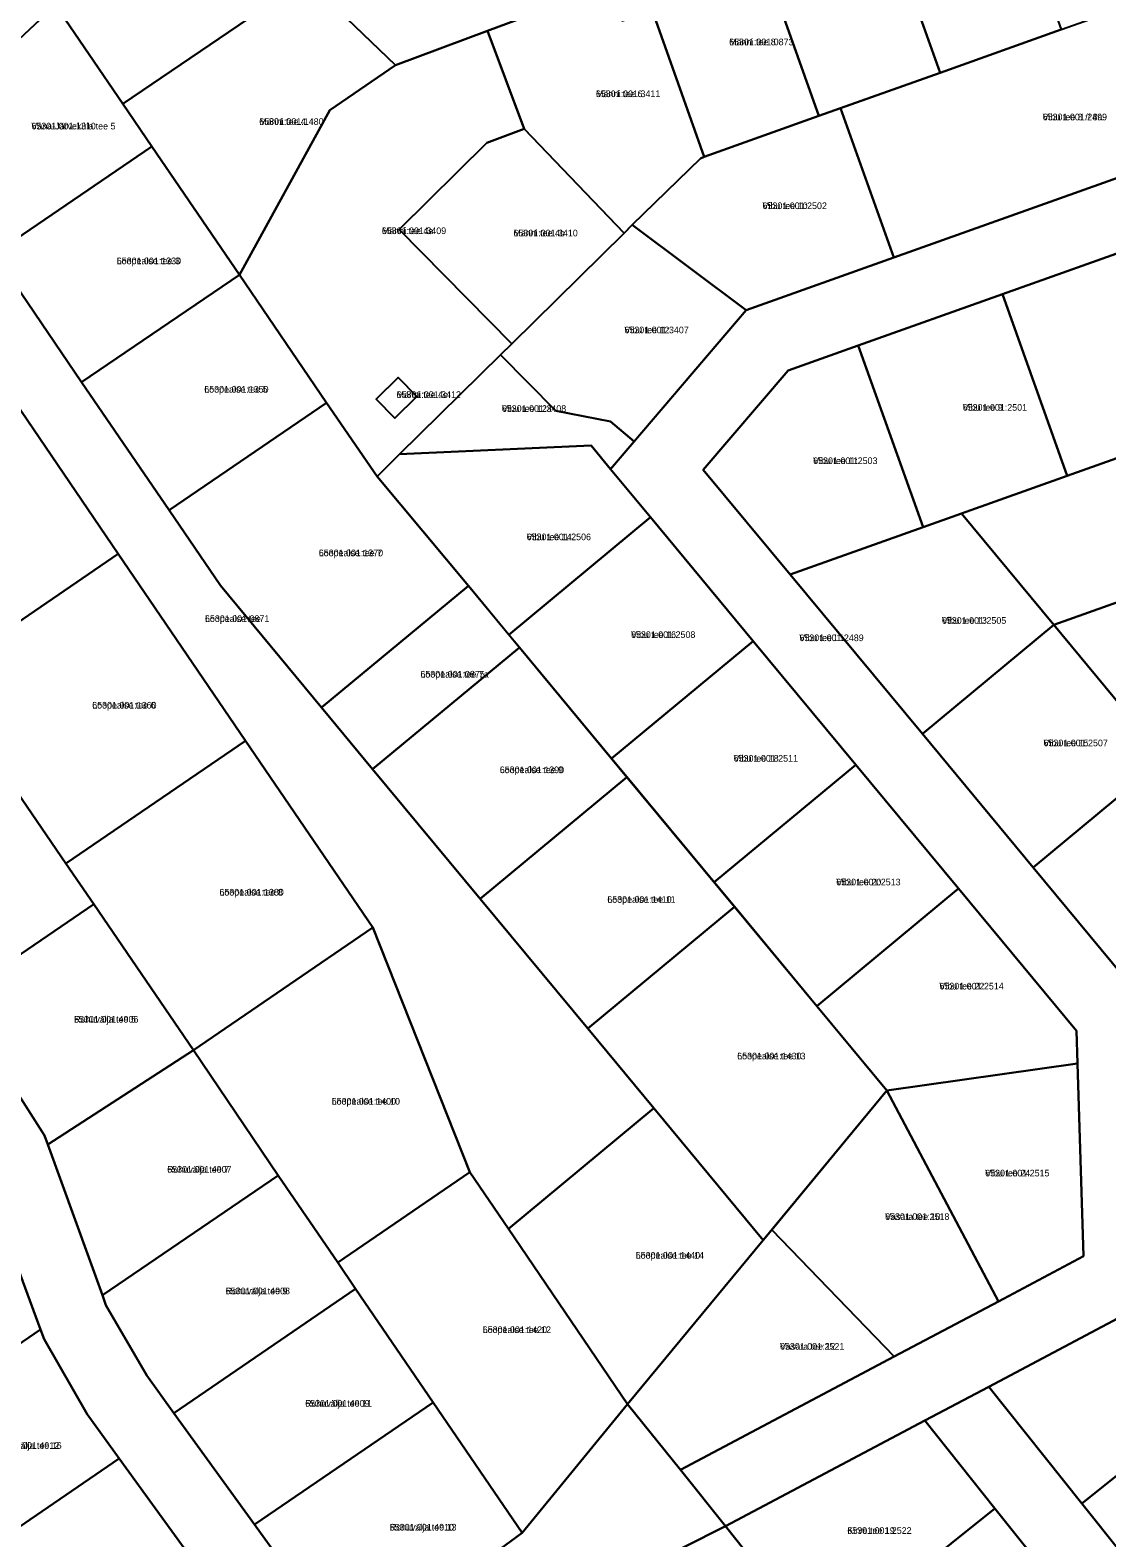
# Model space of a CAD drawing. Extents: x 543236 to 563717, y 6566033 to 6588992.
# Drawn here: x 546092.6 to 546335.4, y 6582727.8 to 6583067.8 of the extents above; entities that cross this region are included whole.
import ezdxf

# ---------------------------------------------------------------- set-up
doc = ezdxf.new("R2010")
doc.units = 0
for name, color, linetype in [('L_AADRESS', 7, 'Continuous'), ('PIIR', 7, 'Continuous'), ('TUNNUS', 7, 'Continuous')]:
    doc.layers.add(name, color=color, linetype=linetype)

msp = doc.modelspace()

# ---------------------------------------------------------------- linework, layer by layer
at = {"layer": 'PIIR'}
for points in [[(546283.16, 6583099.27), (546310.48, 6583109.01), (546325.12, 6583067.92), (546297.81, 6583058.19)], [(546154.84, 6583079.31), (546113.52, 6583051.16), (546098.34, 6583073.44), (546127.23, 6583105.83)], [(546255.85, 6583089.53), (546283.16, 6583099.27), (546297.81, 6583058.19), (546270.49, 6583048.45)], [(546230, 6583080.31), (546255.85, 6583089.53), (546270.49, 6583048.45), (546244.64, 6583039.24), (546232.86, 6583072.31)], [(546120.05, 6583041.58), (546113.52, 6583051.16), (546154.84, 6583079.31), (546175.03, 6583059.92), (546160.16, 6583049.78), (546139.81, 6583012.59)], [(546204.05, 6583045.5), (546195.78, 6583067.66), (546223.31, 6583077.93), (546226.1, 6583069.89), (546232.86, 6583072.31), (546244.64, 6583039.24), (546243.76, 6583038.86), (546228.39, 6583023.86), (546226.54, 6583021.99)], [(546275.38, 6583050.2), (546297.81, 6583058.19), (546325.12, 6583067.92), (546352.44, 6583077.66), (546354.5, 6583078.41), (546366.52, 6583044.72), (546287.4, 6583016.51)], [(546066.56, 6583043.72), (546098.34, 6583073.44), (546113.52, 6583051.16), (546120.05, 6583041.58), (546084.52, 6583017.36)], [(546159.48, 6582983.74), (546139.81, 6583012.59), (546160.16, 6583049.78), (546175.03, 6583059.92), (546195.78, 6583067.66), (546204.05, 6583045.5), (546195.62, 6583042.36), (546175.81, 6583022.87), (546201.2, 6582997.06), (546198.71, 6582994.61), (546175.91, 6582972.15), (546170.9, 6582967.16)], [(546228.39, 6583023.86), (546243.76, 6583038.86), (546244.64, 6583039.24), (546270.49, 6583048.45), (546275.38, 6583050.2), (546287.4, 6583016.51), (546254.11, 6583004.68)], [(546201.2, 6582997.06), (546175.81, 6583022.87), (546195.62, 6583042.36), (546204.05, 6583045.5), (546226.54, 6583021.99)], [(546084.52, 6583017.36), (546120.05, 6583041.58), (546139.81, 6583012.59), (546104.23, 6582988.44)], [(546211.17, 6582981.94), (546198.71, 6582994.61), (546201.2, 6582997.06), (546226.54, 6583021.99), (546228.39, 6583023.86), (546254.11, 6583004.68), (546228.81, 6582975.02), (546223.49, 6582979.57)], [(546311.88, 6583008.25), (546344.42, 6583019.85), (546359.03, 6582978.88), (546326.49, 6582967.28)], [(546104.23, 6582988.44), (546139.81, 6583012.59), (546159.48, 6582983.74), (546123.95, 6582959.52)], [(546279.35, 6582996.65), (546311.88, 6583008.25), (546326.49, 6582967.28), (546302.63, 6582958.77), (546293.96, 6582955.68)], [(546219.11, 6582974.11), (546175.91, 6582972.15), (546198.71, 6582994.61), (546211.17, 6582981.94), (546223.49, 6582979.57), (546228.81, 6582975.02), (546223.5, 6582968.81)], [(546244.42, 6582968.65), (546263.53, 6582991.01), (546279.35, 6582996.65), (546293.96, 6582955.68), (546264.03, 6582945.01)], [(546072.02, 6582922.01), (546068.68, 6582926.94), (546052.49, 6582950.63), (546043.31, 6582964.2), (546083.76, 6582991.84), (546112.48, 6582949.7)], [(546170.65, 6582984.54), (546174.86, 6582980.26), (546179.85, 6582985.17), (546175.64, 6582989.45)], [(546174.86, 6582980.26), (546170.65, 6582984.54), (546175.64, 6582989.45), (546179.85, 6582985.17)], [(546135.52, 6582942.53), (546123.95, 6582959.52), (546159.48, 6582983.74), (546170.9, 6582967.16), (546191.44, 6582942.45), (546158.34, 6582915.01)], [(546302.63, 6582958.77), (546326.49, 6582967.28), (546359.03, 6582978.88), (546369.33, 6582950), (546323.46, 6582933.65)], [(546170.9, 6582967.16), (546175.91, 6582972.15), (546219.11, 6582974.11), (546223.5, 6582968.81), (546232.52, 6582957.93), (546200.57, 6582931.43), (546191.44, 6582942.45)], [(546200.57, 6582931.43), (546232.52, 6582957.93), (546255.66, 6582930.03), (546223.72, 6582903.53), (546202.93, 6582928.59)], [(546264.03, 6582945.01), (546293.96, 6582955.68), (546302.63, 6582958.77), (546323.46, 6582933.65), (546293.83, 6582909.07)], [(546323.46, 6582933.65), (546369.33, 6582950), (546379.19, 6582922.34), (546351.73, 6582899.57), (546348.45, 6582903.53)], [(546072.02, 6582922.01), (546112.48, 6582949.7), (546141.2, 6582907.56), (546100.68, 6582879.88), (546086.42, 6582900.68)], [(546158.34, 6582915.01), (546191.44, 6582942.45), (546202.93, 6582928.59), (546169.83, 6582901.15)], [(546293.83, 6582909.07), (546323.46, 6582933.65), (546348.45, 6582903.53), (546318.81, 6582878.95)], [(546223.72, 6582903.53), (546255.66, 6582930.03), (546278.8, 6582902.12), (546246.86, 6582875.63), (546227.2, 6582899.38)], [(546169.83, 6582901.15), (546202.93, 6582928.59), (546227.19, 6582899.35), (546194.09, 6582871.89)], [(546100.68, 6582879.88), (546141.2, 6582907.56), (546169.92, 6582865.42), (546129.46, 6582837.75), (546106.95, 6582870.69)], [(546318.81, 6582878.95), (546348.45, 6582903.53), (546351.73, 6582899.57), (546374.02, 6582872.69), (546363.72, 6582864.16), (546344.38, 6582848.12)], [(546075.57, 6582849.29), (546049.61, 6582875.54), (546086.42, 6582900.68), (546100.68, 6582879.88), (546106.95, 6582870.69)], [(546194.09, 6582871.89), (546227.19, 6582899.35), (546251.45, 6582870.1), (546218.34, 6582842.65)], [(546246.86, 6582875.63), (546278.8, 6582902.12), (546301.94, 6582874.22), (546270, 6582847.73), (546251.45, 6582870.14)], [(546270, 6582847.73), (546301.94, 6582874.22), (546328.56, 6582842.13), (546328.79, 6582834.77), (546285.79, 6582828.69)], [(546077.18, 6582847.7), (546075.57, 6582849.29), (546106.95, 6582870.69), (546129.46, 6582837.75), (546096.6, 6582816.48), (546095.84, 6582818.55)], [(546233.23, 6582824.7), (546218.34, 6582842.65), (546251.44, 6582870.12), (546285.78, 6582828.71), (546257.91, 6582794.95)], [(546129.46, 6582837.75), (546169.92, 6582865.42), (546191.78, 6582810.25), (546162, 6582789.9), (546148.58, 6582809.53)], [(546108.95, 6582782.56), (546096.6, 6582816.48), (546129.46, 6582837.75), (546148.58, 6582809.53)], [(546285.79, 6582828.69), (546328.79, 6582834.77), (546330.17, 6582791.29), (546310.97, 6582781.12)], [(546259.84, 6582797.26), (546285.79, 6582828.69), (546310.97, 6582781.12), (546287.43, 6582768.66)], [(546200.46, 6582797.52), (546233.23, 6582824.7), (546257.91, 6582794.95), (546227.35, 6582757.93)], [(546109.71, 6582780.25), (546108.95, 6582782.56), (546148.58, 6582809.53), (546162, 6582789.9), (546165.98, 6582783.95), (546125.03, 6582755.93), (546118.95, 6582764.4)], [(546191.78, 6582810.25), (546200.46, 6582797.52), (546227.35, 6582757.93), (546203.59, 6582728.94), (546183.5, 6582758.29), (546165.98, 6582783.95), (546162, 6582789.9)], [(546057.33, 6582749.11), (546040.12, 6582774.36), (546083.98, 6582804.39), (546094.92, 6582774.75)], [(546227.35, 6582757.93), (546257.89, 6582794.95), (546259.84, 6582797.26), (546287.43, 6582768.66), (546239.25, 6582743.17)], [(546143.18, 6582730.78), (546125.03, 6582755.93), (546165.98, 6582783.95), (546183.5, 6582758.29)], [(546308.77, 6582761.86), (546346.48, 6582781.82), (546350.39, 6582783.89), (546356.83, 6582785.82), (546370.8, 6582768.33), (546329.78, 6582735.56)], [(546076.51, 6582720.98), (546057.33, 6582749.11), (546094.92, 6582774.75), (546095.75, 6582772.62), (546105.45, 6582755.7), (546112.72, 6582745.69)], [(546329.78, 6582735.56), (546370.8, 6582768.33), (546388.71, 6582745.9), (546347.69, 6582713.14)], [(546165.04, 6582700.6), (546143.18, 6582730.78), (546183.5, 6582758.29), (546203.59, 6582728.94)], [(546203.59, 6582728.94), (546227.35, 6582757.93), (546239.25, 6582743.17), (546249.39, 6582730.42), (546202, 6582706.52), (546188.37, 6582698.53), (546161.08, 6582678.83), (546152.11, 6582691.1), (546165.04, 6582700.6)], [(546270.04, 6582704.5), (546249.39, 6582730.42), (546294.38, 6582754.24), (546310.19, 6582734.45), (546271.12, 6582703.16)], [(546095.63, 6582692.93), (546076.51, 6582720.98), (546112.72, 6582745.69), (546132.67, 6582718.11)], [(546288.65, 6582681.16), (546271.12, 6582703.16), (546310.19, 6582734.45), (546328.91, 6582711.01), (546289.84, 6582679.73)], [(546202, 6582706.52), (546249.39, 6582730.42), (546270.04, 6582704.5), (546229.48, 6582672.36)]]:
    msp.add_lwpolyline(points, close=True, dxfattribs=at)
for points in [[(546098.34, 6583073.44), (546066.56, 6583043.72), (546084.52, 6583017.36), (546104.23, 6582988.44), (546123.95, 6582959.52), (546135.52, 6582942.53), (546158.34, 6582915.01), (546169.83, 6582901.15), (546194.09, 6582871.89), (546218.34, 6582842.65), (546233.23, 6582824.7), (546200.46, 6582797.52), (546191.78, 6582810.25), (546169.92, 6582865.42), (546141.2, 6582907.56), (546112.48, 6582949.7), (546083.76, 6582991.84), (546055.32, 6583033.57), (546014.84, 6583005.81), (546008.22, 6583015.56), (546049.76, 6583042.52), (546091.31, 6583079.59)], [(546223.31, 6583077.93), (546195.78, 6583067.66), (546175.03, 6583059.92), (546154.84, 6583079.31)], [(546346.48, 6582781.82), (546308.77, 6582761.86), (546294.38, 6582754.24), (546249.39, 6582730.42), (546239.25, 6582743.17), (546287.43, 6582768.66), (546310.97, 6582781.12), (546330.17, 6582791.29), (546328.79, 6582834.77), (546328.56, 6582842.13), (546301.94, 6582874.22), (546278.8, 6582902.12), (546255.66, 6582930.03), (546232.52, 6582957.93), (546223.5, 6582968.81), (546254.11, 6583004.68), (546287.4, 6583016.51), (546366.52, 6583044.72)], [(546344.42, 6583019.85), (546311.88, 6583008.25), (546279.35, 6582996.65), (546263.53, 6582991.01), (546244.42, 6582968.65), (546264.03, 6582945.01), (546293.83, 6582909.07), (546318.81, 6582878.95), (546344.38, 6582848.12)], [(546077.18, 6582847.7), (546095.84, 6582818.55), (546096.6, 6582816.48), (546108.95, 6582782.56), (546109.71, 6582780.25), (546118.95, 6582764.4), (546125.03, 6582755.93), (546143.18, 6582730.78), (546165.04, 6582700.6), (546152.11, 6582691.1), (546132.67, 6582718.11), (546112.72, 6582745.69), (546105.45, 6582755.7), (546095.75, 6582772.62), (546094.92, 6582774.75), (546083.98, 6582804.39)], [(546328.91, 6582711.01), (546310.19, 6582734.45), (546294.38, 6582754.24), (546308.77, 6582761.86), (546329.78, 6582735.56), (546347.69, 6582713.14)]]:
    msp.add_lwpolyline(points, dxfattribs=at)

# ---------------------------------------------------------------- texts
at = {"layer": 'L_AADRESS'}
for s, p in [('Männi tee 8', (546250.25, 6583064.38)), ('Männi tee 6', (546220.21, 6583052.69)), ('Vibu tee 8 // 8a', (546320.95, 6583047.46)), ('Vana-Järveküla tee 5', (546092.9, 6583045.4)), ('Männi tee 4', (546144.28, 6583046.43)), ('Vibu tee 10', (546257.78, 6583027.44)), ('Männi tee 4a', (546171.93, 6583021.8)), ('Männi tee 4b', (546201.6, 6583021.28)), ('Loopealse tee 3', (546112.14, 6583015.01)), ('Vibu tee 12', (546226.63, 6582999.44)), ('Loopealse tee 5', (546131.88, 6582986.05)), ('Männi tee 4c', (546175.25, 6582984.86)), ('Vibu tee 12a', (546198.99, 6582981.71)), ('Vibu tee 9', (546302.92, 6582981.96)), ('Vibu tee 11', (546269.19, 6582969.94)), ('Vibu tee 14', (546204.58, 6582952.77)), ('Loopealse tee 7', (546157.7, 6582949.16)), ('Loopealse tee', (546132.04, 6582934.33)), ('Vibu tee 13', (546298.23, 6582933.92)), ('Vibu tee 16', (546228.12, 6582930.73)), ('Vibu tee L1', (546266.08, 6582930.01)), ('Loopealse tee 7a', (546180.63, 6582921.8)), ('Loopealse tee 6', (546106.61, 6582914.81)), ('Vibu tee 15', (546321.14, 6582906.3)), ('Vibu tee 18', (546251.26, 6582902.83)), ('Loopealse tee 9', (546198.52, 6582900.24)), ('Vibu tee 20', (546274.4, 6582874.93)), ('Loopealse tee 8', (546135.3, 6582872.64)), ('Loopealse tee 11', (546222.77, 6582871)), ('Vibu tee 22', (546297.66, 6582851.46)), ('Rohuvälja tee 5', (546102.52, 6582843.99)), ('Loopealse tee 13', (546252.06, 6582835.69)), ('Loopealse tee 10', (546160.62, 6582825.49)), ('Rohuvälja tee 7', (546123.53, 6582810.15)), ('Vibu tee 24', (546307.98, 6582809.3)), ('Vasara tee 10', (546285.41, 6582799.49)), ('Loopealse tee 14', (546229.18, 6582790.75)), ('Rohuvälja tee 9', (546136.7, 6582782.73)), ('Loopealse tee 12', (546194.68, 6582773.98)), ('Vasara tee 12', (546261.71, 6582770.22)), ('Rohuvälja tee 11', (546154.64, 6582757.37)), ('Rohuvälja tee 16', (546084.66, 6582747.87)), ('Rohuvälja tee 13', (546173.7, 6582729.45)), ('Kirve tee 19', (546276.89, 6582728.7))]:
    msp.add_text(s, height=1.5, dxfattribs=at).set_placement(p)
at = {"layer": 'TUNNUS'}
for s, p in [('65301:001:0873', (546250.25, 6583064.38)), ('65301:001:3411', (546220.21, 6583052.69)), ('65301:001:2499', (546320.95, 6583047.46)), ('65301:001:1310', (546092.9, 6583045.4)), ('65301:001:1480', (546144.28, 6583046.43)), ('65301:001:2502', (546257.78, 6583027.44)), ('65301:001:3409', (546171.93, 6583021.8)), ('65301:001:3410', (546201.6, 6583021.28)), ('65301:001:1330', (546112.14, 6583015.01)), ('65301:001:3407', (546226.63, 6582999.44)), ('65301:001:1350', (546131.88, 6582986.05)), ('65301:001:3412', (546175.25, 6582984.86)), ('65301:001:3408', (546198.99, 6582981.71)), ('65301:001:2501', (546302.92, 6582981.96)), ('65301:001:2503', (546269.19, 6582969.94)), ('65301:001:2506', (546204.58, 6582952.77)), ('65301:001:1370', (546157.7, 6582949.16)), ('65301:001:0871', (546132.04, 6582934.33)), ('65301:001:2505', (546298.23, 6582933.92)), ('65301:001:2508', (546228.12, 6582930.73)), ('65301:001:2489', (546266.08, 6582930.01)), ('65301:001:0875', (546180.63, 6582921.8)), ('65301:001:1360', (546106.61, 6582914.81)), ('65301:001:2507', (546321.14, 6582906.3)), ('65301:001:2511', (546251.26, 6582902.83)), ('65301:001:1390', (546198.52, 6582900.24)), ('65301:001:2513', (546274.4, 6582874.93)), ('65301:001:1380', (546135.3, 6582872.64)), ('65301:001:1410', (546222.77, 6582871)), ('65301:001:2514', (546297.66, 6582851.46)), ('65301:001:4906', (546102.52, 6582843.99)), ('65301:001:1430', (546252.06, 6582835.69)), ('65301:001:1400', (546160.62, 6582825.49)), ('65301:001:4907', (546123.53, 6582810.15)), ('65301:001:2515', (546307.98, 6582809.3)), ('65301:001:2518', (546285.41, 6582799.49)), ('65301:001:1440', (546229.18, 6582790.75)), ('65301:001:4908', (546136.7, 6582782.73)), ('65301:001:1420', (546194.68, 6582773.98)), ('65301:001:2521', (546261.71, 6582770.22)), ('65301:001:4909', (546154.64, 6582757.37)), ('65301:001:4912', (546084.66, 6582747.87)), ('65301:001:4910', (546173.7, 6582729.45)), ('65301:001:2522', (546276.89, 6582728.7))]:
    msp.add_text(s, height=1.5, dxfattribs=at).set_placement(p)

doc.saveas('drawing.dxf')
